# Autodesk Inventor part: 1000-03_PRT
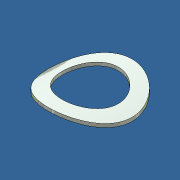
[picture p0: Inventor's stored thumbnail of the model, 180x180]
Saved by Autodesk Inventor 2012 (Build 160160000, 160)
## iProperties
Created: 2007-03
Part Number: 1000-03_PRT
Document SubType Name: Modeling
Designer: Andy Moles
Material: Steel
Mass: 0.484358 g
Surface Area: 2.54827 cm^2
Volume: 0.0617016 cm^3
Density: 7.85 g/cm^3
Author: Andy Moles
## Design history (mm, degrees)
feature "Base1"
body "Solid1"
